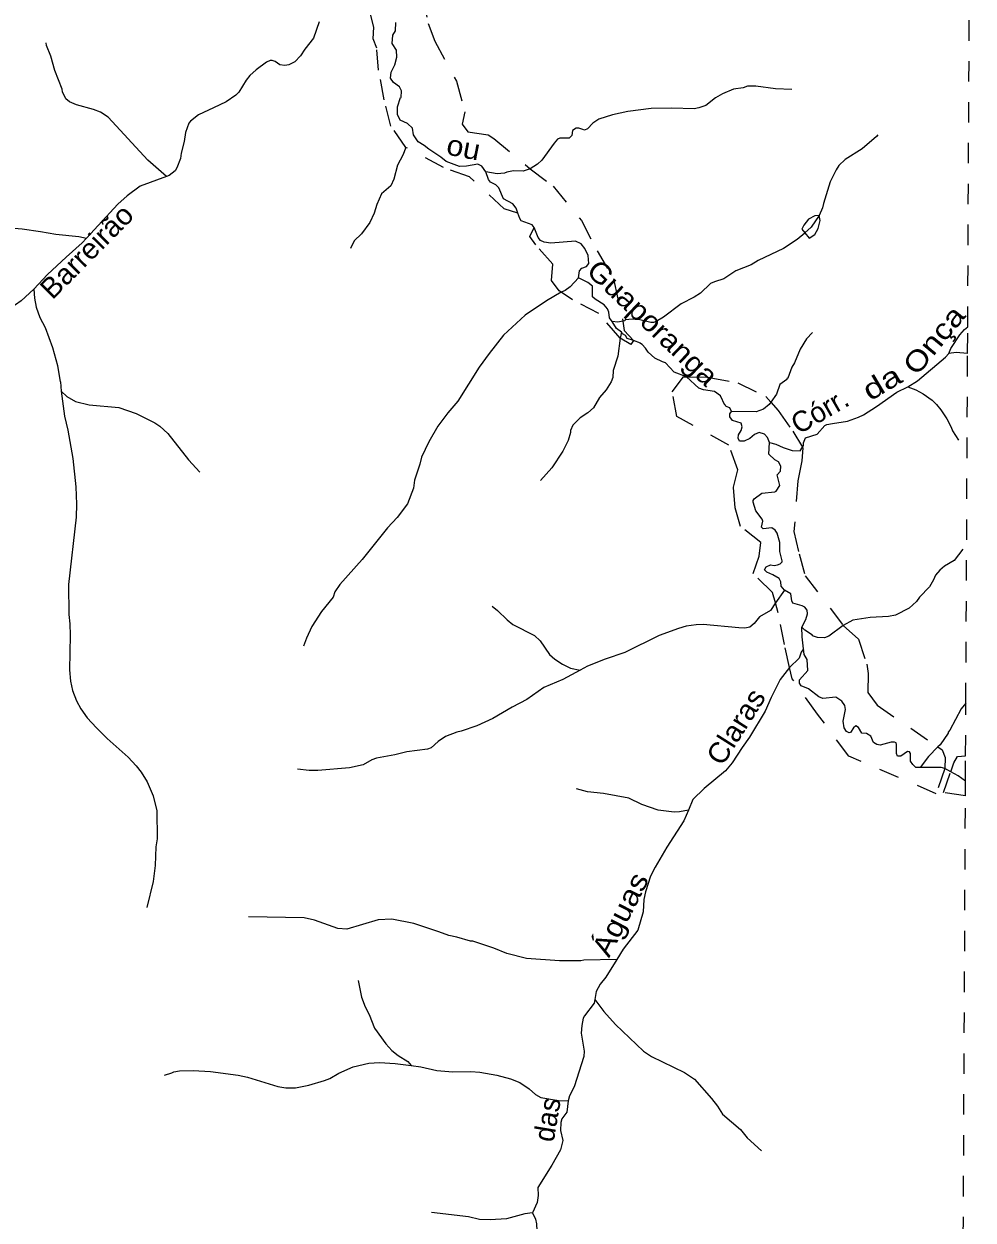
# Model space of a CAD drawing. Extents: x 551.6 to 577.6, y 7567 to 7594.7.
# Drawn here: x 572.91 to 577.56, y 7584.89 to 7590.74 of the extents above; entities that cross this region are included whole.
import ezdxf
from ezdxf.enums import TextEntityAlignment as Align

# ---------------------------------------------------------------- set-up
doc = ezdxf.new("R2010")
doc.units = 0
doc.header["$LTSCALE"] = 0.04
doc.linetypes.add('SHORT_DASHED', pattern=[2.7, 1.5, -1.2])
for name, color, linetype, lineweight in [('2', 7, 'Continuous', 25), ('21', 7, 'SHORT_DASHED', 13), ('53', 7, 'SHORT_DASHED', 13), ('55', 7, 'Continuous', 25), ('7', 7, 'Continuous', 25)]:
    doc.layers.add(name, color=color, linetype=linetype, lineweight=lineweight)
doc.layers.add('61', color=7, linetype='Continuous')

msp = doc.modelspace()

# ---------------------------------------------------------------- linework, layer by layer
at = {"layer": '2'}
for points in [[(576.8021, 7589.8034), (576.7803, 7589.8018), (576.7501, 7589.7864), (576.7265, 7589.7562), (576.7172, 7589.7366), (576.7322, 7589.7187)], [(576.781, 7589.7119), (576.7973, 7589.7407), (576.8076, 7589.7805), (576.8021, 7589.8034)], [(576.7322, 7589.7187), (576.7534, 7589.6932), (576.781, 7589.7119)]]:
    msp.add_lwpolyline(points, dxfattribs=at)
at = {"layer": '21'}
for p, q in [((577.4113, 7586.9802), (577.4465, 7587.0816)), ((577.518, 7586.9644), (577.4113, 7586.9802))]:
    msp.add_line(p, q, dxfattribs=at)
for points in [[(574.7788, 7590.1378), (574.7064, 7590.2422), (574.6729, 7590.3709), (574.6461, 7590.5153), (574.6372, 7590.6224), (574.6201, 7590.6693), (574.6231, 7590.7258), (574.5903, 7590.8538), (574.5501, 7590.8925), (574.4851, 7590.8927)], [(574.8652, 7590.8839), (574.8641, 7590.8725), (574.8879, 7590.7438), (574.9214, 7590.6567), (575.0267, 7590.4621), (575.0688, 7590.3122), (575.0554, 7590.2519), (575.0833, 7590.2143), (575.1823, 7590.1987), (575.2106, 7590.1816), (575.3873, 7590.0333)], [(575.3278, 7589.8154), (575.2602, 7589.8375), (575.0913, 7589.993), (574.9632, 7590.0391), (574.7788, 7590.1378)], [(575.3873, 7590.0333), (575.5009, 7589.9472), (575.6393, 7589.7798), (575.7153, 7589.6309), (575.7953, 7589.4936), (575.8416, 7589.287)], [(575.5402, 7589.4283), (575.5304, 7589.4349), (575.4917, 7589.4855), (575.4985, 7589.5666), (575.4151, 7589.6604), (575.3868, 7589.702), (575.408, 7589.7462)], [(575.8281, 7589.2037), (575.7239, 7589.3247), (575.5944, 7589.3917), (575.5402, 7589.4283)], [(575.8416, 7589.287), (575.8475, 7589.2414), (575.8935, 7589.1929)], [(575.8935, 7589.1929), (575.8802, 7589.173), (575.8281, 7589.2037)], [(576.5882, 7587.9092), (576.5744, 7587.9589), (576.4784, 7588.0522), (576.5085, 7588.1372), (576.5168, 7588.203), (576.418, 7588.2825), (576.3905, 7588.373), (576.3823, 7588.4745), (576.4043, 7588.5595), (576.3604, 7588.6802), (576.1052, 7588.82), (576.0833, 7588.9407), (576.1382, 7589.0147), (576.1523, 7589.0144)], [(576.1523, 7589.0144), (576.2644, 7589.012), (576.4044, 7588.9846), (576.5416, 7588.9187), (576.566, 7588.891)], [(576.566, 7588.891), (576.6019, 7588.8502), (576.6733, 7588.7487), (576.7206, 7588.67)], [(576.7206, 7588.67), (576.7227, 7588.6665), (576.7172, 7588.6034), (576.698, 7588.5047), (576.6788, 7588.2578), (576.7035, 7588.1481), (576.7337, 7588.0412), (576.92, 7587.7979)], [(576.6578, 7587.5914), (576.632, 7587.7039), (576.6018, 7587.8602), (576.5882, 7587.9092)], [(576.92, 7587.7979), (576.9944, 7587.7313), (577.0347, 7587.6079), (577.0425, 7587.5625), (577.0406, 7587.4689), (577.0859, 7587.4078), (577.3828, 7587.203)], [(577.4169, 7587.0981), (577.3748, 7586.9743), (576.9469, 7587.1582), (576.7939, 7587.3639), (576.6704, 7587.5366), (576.6578, 7587.5914)], [(577.3828, 7587.203), (577.4044, 7587.1881), (577.4192, 7587.1516), (577.4169, 7587.0981)], [(577.4465, 7587.0816), (577.4616, 7587.125), (577.4793, 7587.1566), (577.519, 7587.1599)]]:
    msp.add_lwpolyline(points, dxfattribs=at)
at = {"layer": '53'}
msp.add_lwpolyline([(577.4204, 7566.9518), (577.4226, 7567.3928), (577.4384, 7570.6314), (577.4446, 7571.9213), (577.4462, 7572.242), (577.4659, 7576.2813), (577.4696, 7577.0412), (577.4755, 7578.252), (577.4832, 7579.8317), (577.4989, 7583.0336), (577.5065, 7584.6034), (577.518, 7586.9644), (577.5184, 7587.0352), (577.519, 7587.1599), (577.5202, 7587.417), (577.5286, 7589.1281), (577.5292, 7589.2596), (577.5446, 7592.4063), (577.549, 7593.3187), (577.5554, 7594.6251)], dxfattribs=at)
at = {"layer": '55'}
msp.add_lwpolyline([(576.8021, 7589.8034), (576.7637, 7589.747), (576.7322, 7589.7187), (576.732, 7589.7185)], dxfattribs=at)
at = {"layer": '7'}
for p, q in [((575.835, 7589.2333), (575.8281, 7589.2037)), ((576.6324, 7587.9708), (576.5882, 7587.9092))]:
    msp.add_line(p, q, dxfattribs=at)
for points in [[(574.3546, 7590.7519), (574.3281, 7590.6722), (574.2846, 7590.6183), (574.2645, 7590.5861), (574.2363, 7590.5555), (574.2074, 7590.541), (574.1865, 7590.5386), (574.1631, 7590.541), (574.1398, 7590.5579), (574.1253, 7590.5627), (574.1156, 7590.5627), (574.0979, 7590.5539), (574.0464, 7590.5169), (574.0158, 7590.4895), (573.9981, 7590.467), (573.9627, 7590.4082), (573.9466, 7590.3929), (573.9, 7590.3607), (573.8388, 7590.331)], [(574.839, 7590.1647), (574.8177, 7590.1993), (574.8126, 7590.2312), (574.7868, 7590.2537), (574.7514, 7590.2706), (574.7385, 7590.298), (574.7386, 7590.3359), (574.7534, 7590.3815), (574.7562, 7590.3817), (574.7578, 7590.4139), (574.7482, 7590.4332), (574.7192, 7590.4549), (574.7039, 7590.4766), (574.7071, 7590.5056), (574.7257, 7590.541), (574.7349, 7590.579), (574.7334, 7590.6136), (574.7128, 7590.646), (574.7157, 7590.6873), (574.7283, 7590.7087), (574.7298, 7590.7485)], [(573.6077, 7589.9951), (573.516, 7590.0742), (573.3229, 7590.2851), (573.2851, 7590.31), (573.2513, 7590.3237), (573.1676, 7590.3454), (573.1338, 7590.3599), (573.1161, 7590.3752), (573.0984, 7590.409), (573.0967, 7590.4219), (573.0613, 7590.5137), (573.042, 7590.5845), (573.0211, 7590.636), (573.0187, 7590.6497)], [(576.6677, 7590.4203), (576.588, 7590.4235), (576.493, 7590.4364), (576.4512, 7590.4364), (576.4302, 7590.4291), (576.3836, 7590.4219), (576.3288, 7590.4002), (576.295, 7590.3809), (576.2468, 7590.343), (576.2129, 7590.3318), (576.1904, 7590.3269), (576.081, 7590.3294), (575.9796, 7590.3277), (575.8653, 7590.3133), (575.7912, 7590.2964), (575.7236, 7590.2762), (575.6938, 7590.2553), (575.6689, 7590.2288), (575.6544, 7590.2215), (575.6448, 7590.2247)], [(573.8388, 7590.331), (573.7647, 7590.2972), (573.7253, 7590.2666), (573.718, 7590.2561), (573.7003, 7590.2111), (573.6939, 7590.166), (573.6794, 7590.1089), (573.6762, 7590.0839), (573.6585, 7590.0372), (573.6497, 7590.0235), (573.6215, 7590.0002), (573.6077, 7589.9951)], [(575.6448, 7590.2247), (575.6254, 7590.2312), (575.6125, 7590.2312), (575.5948, 7590.2199), (575.5916, 7590.1958), (575.5795, 7590.1829), (575.5337, 7590.1829), (575.5224, 7590.1772), (575.5047, 7590.1587), (575.4452, 7590.075), (575.4242, 7590.0549), (575.3873, 7590.0333)], [(577.0886, 7590.199), (577.0821, 7590.1901), (577.0129, 7590.1306), (576.9292, 7590.0775), (576.8986, 7590.0493), (576.8849, 7590.0276), (576.8568, 7589.9696), (576.823, 7589.8634), (576.8189, 7589.8409), (576.8021, 7589.8034)], [(574.7788, 7590.1378), (574.7643, 7590.1), (574.7385, 7590.0501), (574.72, 7589.9825), (574.7056, 7589.9495), (574.6605, 7589.9101), (574.6371, 7589.8586), (574.6243, 7589.8159), (574.6025, 7589.77), (574.5623, 7589.7137), (574.5261, 7589.6799), (574.5084, 7589.6421)], [(575.1706, 7590.0176), (575.1507, 7590.0463), (575.1313, 7590.0557), (575.0766, 7590.046), (575.0412, 7590.0444), (574.977, 7590.0681), (574.951, 7590.0903), (574.8915, 7590.1289), (574.8689, 7590.1474), (574.839, 7590.1647)], [(572.0883, 7590.0759), (572.1841, 7590.0597), (572.2372, 7590.0372), (572.2887, 7590.0219), (572.3403, 7589.9962), (572.469, 7589.9406), (572.5189, 7589.906), (572.5455, 7589.8916), (572.5842, 7589.8514), (572.6155, 7589.8111), (572.6396, 7589.7861), (572.6565, 7589.7732), (572.6815, 7589.7612), (572.704, 7589.7547), (572.902, 7589.7394), (572.9921, 7589.7266), (573.0662, 7589.7121)], [(575.3873, 7590.0333), (575.3534, 7590.0211), (575.3067, 7590.0227), (575.2729, 7590.0163), (575.2617, 7590.0106), (575.2267, 7590.008), (575.1706, 7590.0176)], [(575.3278, 7589.8154), (575.3195, 7589.8398), (575.3033, 7589.8612), (575.2572, 7589.8851), (575.2344, 7589.9389), (575.2204, 7589.9537), (575.1941, 7589.968), (575.1836, 7589.9809), (575.1706, 7590.0176)], [(573.6077, 7589.9951), (573.4798, 7589.9479), (573.4163, 7589.9012), (573.3704, 7589.8594), (573.2166, 7589.6935)], [(575.408, 7589.7462), (575.3969, 7589.758), (575.3439, 7589.7786), (575.3365, 7589.7897), (575.3278, 7589.8154)], [(575.625, 7589.4998), (575.6291, 7589.5328), (575.6413, 7589.5457), (575.6634, 7589.5538), (575.6752, 7589.5685), (575.6722, 7589.6076), (575.6556, 7589.6419), (575.6372, 7589.6654), (575.6099, 7589.678), (575.4886, 7589.6694), (575.4564, 7589.6742), (575.4386, 7589.6825), (575.4264, 7589.6961), (575.408, 7589.7462)], [(573.0662, 7589.7121), (573.1789, 7589.7008), (573.2166, 7589.6935)], [(573.2166, 7589.6935), (573.1957, 7589.671), (573.1169, 7589.6002)], [(576.732, 7589.7185), (576.695, 7589.6863), (576.6282, 7589.642), (576.5035, 7589.5841), (576.4689, 7589.5632), (576.3948, 7589.5326), (576.3353, 7589.4948), (576.2902, 7589.4803), (576.2709, 7589.4706), (576.221, 7589.4248), (576.1904, 7589.4046), (576.1276, 7589.3716), (576.0407, 7589.3065), (576.0037, 7589.2855), (575.9908, 7589.2799), (575.9779, 7589.2807), (575.9175, 7589.2955), (575.8887, 7589.2969), (575.8533, 7589.2933), (575.8508, 7589.2888), (575.8416, 7589.287)], [(573.1169, 7589.6002), (573.0259, 7589.5157), (572.9581, 7589.4442)], [(575.625, 7589.4998), (575.5837, 7589.4548), (575.5594, 7589.4364), (575.5402, 7589.4283)], [(575.7884, 7589.2854), (575.7767, 7589.3033), (575.7735, 7589.3314), (575.767, 7589.3475), (575.7502, 7589.3668), (575.7054, 7589.3939), (575.6932, 7589.4068), (575.6925, 7589.4591), (575.6704, 7589.4768), (575.625, 7589.4998)], [(572.9581, 7589.4442), (572.8964, 7589.3869), (572.8698, 7589.3676), (572.8392, 7589.3523), (572.8183, 7589.3483), (572.7555, 7589.3588), (572.7362, 7589.3588), (572.6589, 7589.329), (572.6203, 7589.2992), (572.6012, 7589.2752)], [(572.9581, 7589.4442), (572.9615, 7589.3998), (572.9704, 7589.3548), (572.9881, 7589.3049), (573.0138, 7589.2566), (573.0509, 7589.1584), (573.0742, 7589.0699), (573.0871, 7588.9901), (573.0896, 7588.9901), (573.0933, 7588.9451)], [(575.5402, 7589.4283), (575.4677, 7589.3869), (575.3639, 7589.3169), (575.2568, 7589.2179), (575.1876, 7589.1294), (575.1385, 7589.0618), (575.0339, 7588.896), (574.9848, 7588.8381), (574.9357, 7588.7737), (574.8914, 7588.6964), (574.856, 7588.6208), (574.848, 7588.587), (574.8222, 7588.5081), (574.8166, 7588.4695), (574.7876, 7588.3922)], [(575.8416, 7589.287), (575.817, 7589.2823), (575.7884, 7589.2854)], [(575.835, 7589.2333), (575.8105, 7589.2517), (575.7884, 7589.2854)], [(577.436, 7589.1282), (577.447, 7589.154), (577.4909, 7589.2196), (577.5127, 7589.2461), (577.5292, 7589.2596)], [(575.8281, 7589.2037), (575.817, 7589.1149), (575.7944, 7589.0457), (575.792, 7589.0119), (575.7848, 7588.9894), (575.759, 7588.9507), (575.7276, 7588.9137), (575.6979, 7588.8622), (575.6705, 7588.8381), (575.6327, 7588.8131), (575.5973, 7588.7777), (575.5852, 7588.752), (575.5852, 7588.7415), (575.5739, 7588.7029), (575.5482, 7588.6514), (575.4934, 7588.5693), (575.4387, 7588.5073)], [(575.8935, 7589.1929), (575.8628, 7589.2018), (575.854, 7589.2163), (575.8395, 7589.2243), (575.835, 7589.2333)], [(576.7691, 7589.2316), (576.7401, 7589.2002), (576.7095, 7589.1503), (576.6813, 7589.0827), (576.6684, 7589.0618), (576.6483, 7589.0075), (576.6443, 7589.0071), (576.6443, 7589.0023), (576.6105, 7588.9765), (576.5936, 7588.9298), (576.566, 7588.891)], [(576.0359, 7589.0883), (575.9972, 7589.1053), (575.9659, 7589.1358), (575.9522, 7589.1552), (575.9361, 7589.1729), (575.928, 7589.1769), (575.928, 7589.1801), (575.8935, 7589.1929)], [(576.1523, 7589.0144), (576.093, 7589.0376), (576.0503, 7589.0827), (576.0359, 7589.0883)], [(577.2833, 7588.995), (577.4201, 7589.1109), (577.436, 7589.1282)], [(577.5286, 7589.1281), (577.4733, 7589.1342), (577.436, 7589.1282)], [(576.373, 7588.8456), (576.3649, 7588.8626), (576.3464, 7588.87), (576.3433, 7588.8759), (576.3401, 7588.8759), (576.3191, 7588.9218), (576.2902, 7588.9435), (576.2354, 7588.9514), (576.2125, 7588.9595), (576.1523, 7589.0144)], [(576.7206, 7588.67), (576.7248, 7588.6787), (576.7248, 7588.6916), (576.7361, 7588.7165), (576.7932, 7588.7334), (576.8294, 7588.7761), (576.8391, 7588.7809), (576.8681, 7588.7866), (576.9405, 7588.7978), (576.9952, 7588.8179), (577.0185, 7588.8292), (577.0829, 7588.8694), (577.1827, 7588.9395), (577.2358, 7588.9652), (577.2833, 7588.995)], [(577.2358, 7588.9652), (577.2753, 7588.9515), (577.3107, 7588.9314), (577.3549, 7588.9008), (577.3767, 7588.8799), (577.3984, 7588.8533), (577.4266, 7588.8091), (577.4475, 7588.7689), (577.4539, 7588.7495), (577.4837, 7588.7053)], [(573.0933, 7588.9451), (573.1096, 7588.822), (573.1257, 7588.7528), (573.1499, 7588.6143), (573.1643, 7588.4759), (573.1676, 7588.3906)], [(573.0933, 7588.9451), (573.1209, 7588.9185), (573.1628, 7588.8944), (573.2304, 7588.8767), (573.3752, 7588.8638), (573.4589, 7588.8348), (573.5515, 7588.7898), (573.5756, 7588.7737), (573.6142, 7588.7367), (573.7156, 7588.6079), (573.7712, 7588.5475)], [(576.5596, 7588.6932), (576.5492, 7588.7175), (576.5345, 7588.7337), (576.5079, 7588.7426), (576.4851, 7588.7322), (576.4633, 7588.7134), (576.4357, 7588.6998), (576.4128, 7588.699), (576.4054, 7588.7145), (576.4069, 7588.73), (576.4209, 7588.7521), (576.4246, 7588.7705), (576.4202, 7588.7882), (576.3781, 7588.8007), (576.3656, 7588.8184), (576.3656, 7588.8339), (576.373, 7588.8456)], [(576.566, 7588.891), (576.5572, 7588.8787), (576.5299, 7588.8566), (576.4938, 7588.8426), (576.373, 7588.8456)], [(576.5976, 7588.0944), (576.6121, 7588.0992), (576.621, 7588.1089), (576.6218, 7588.1137), (576.6105, 7588.1604), (576.6089, 7588.2039), (576.5968, 7588.249), (576.5871, 7588.2643), (576.5713, 7588.275), (576.5289, 7588.2709), (576.5201, 7588.2791), (576.5268, 7588.3077), (576.5228, 7588.3182), (576.4922, 7588.3584), (576.4785, 7588.4019), (576.4785, 7588.4099), (576.4841, 7588.418), (576.522, 7588.4453), (576.5848, 7588.4517), (576.5912, 7588.455), (576.6093, 7588.4822), (576.5967, 7588.5345), (576.6122, 7588.5522), (576.6144, 7588.5779), (576.6026, 7588.5978), (576.5857, 7588.6089), (576.5555, 7588.6361), (576.5596, 7588.6932)], [(576.5596, 7588.6932), (576.5908, 7588.6848), (576.6266, 7588.6682), (576.6701, 7588.6546), (576.7087, 7588.653), (576.7206, 7588.67)], [(573.1676, 7588.3906), (573.166, 7588.3278), (573.1289, 7587.9979), (573.1305, 7587.8514), (573.1354, 7587.8063), (573.137, 7587.75), (573.133, 7587.581), (573.1386, 7587.5246), (573.1474, 7587.4796), (573.1684, 7587.4281), (573.1893, 7587.3894)], [(574.7876, 7588.3922), (574.7369, 7588.3262), (574.6894, 7588.2747), (574.5655, 7588.121), (574.456, 7587.9979), (574.4327, 7587.9625), (574.4231, 7587.9367), (574.3667, 7587.8667), (574.32, 7587.7918), (574.2927, 7587.7355), (574.279, 7587.6961)], [(577.5046, 7588.1709), (577.4628, 7588.1161), (577.4153, 7588.088), (577.392, 7588.0687), (577.3718, 7588.0445), (577.3622, 7588.0204), (577.3429, 7587.9866), (577.293, 7587.9359), (577.2785, 7587.9142), (577.2431, 7587.8828), (577.1755, 7587.8482), (577.1417, 7587.8417), (577.0516, 7587.8361), (576.9662, 7587.824), (576.92, 7587.7979)], [(576.6324, 7587.9708), (576.6169, 7587.9907), (576.6147, 7588.0106), (576.6058, 7588.0276), (576.5756, 7588.046), (576.5461, 7588.059), (576.5352, 7588.0694), (576.5429, 7588.0838), (576.5636, 7588.0941), (576.5813, 7588.0919), (576.5976, 7588.0944)], [(576.718, 7587.7888), (576.7371, 7587.8271), (576.7448, 7587.8547), (576.7441, 7587.8724), (576.7323, 7587.8864), (576.7183, 7587.8932), (576.6729, 7587.906), (576.6678, 7587.9185), (576.6633, 7587.9524), (576.6324, 7587.9708)], [(576.5882, 7587.9092), (576.5646, 7587.8707), (576.5099, 7587.8393), (576.4833, 7587.8079), (576.4632, 7587.7894), (576.4383, 7587.7846), (576.4093, 7587.7854), (576.2339, 7587.8031), (576.2001, 7587.8015), (576.1518, 7587.7934), (576.114, 7587.783), (576.0198, 7587.7484), (575.8508, 7587.6647), (575.7542, 7587.6325)], [(575.2013, 7587.8924), (575.2287, 7587.8715), (575.2754, 7587.8248), (575.3027, 7587.8031), (575.4097, 7587.7492), (575.4371, 7587.7226), (575.4822, 7587.655), (575.5079, 7587.6325), (575.5466, 7587.6083), (575.5852, 7587.589), (575.6327, 7587.5787)], [(576.92, 7587.7979), (576.8487, 7587.7451), (576.8278, 7587.7363), (576.794, 7587.7387), (576.7699, 7587.7475), (576.7699, 7587.75), (576.7319, 7587.7739), (576.718, 7587.7888)], [(576.7262, 7587.6839), (576.7187, 7587.7417), (576.718, 7587.7888)], [(576.7262, 7587.6839), (576.7135, 7587.6663), (576.7039, 7587.6381), (576.6578, 7587.5914)], [(577.2961, 7587.1026), (577.2756, 7587.1025), (577.2608, 7587.1165), (577.249, 7587.1335), (577.2498, 7587.171), (577.2439, 7587.1793), (577.2342, 7587.181), (577.2013, 7587.158), (577.1858, 7587.158), (577.1814, 7587.1705), (577.1806, 7587.2154), (577.1784, 7587.2228), (577.1711, 7587.2268), (577.1545, 7587.2257), (577.1014, 7587.2124), (577.0845, 7587.2154), (577.0682, 7587.2242), (577.055, 7587.2566), (577.0336, 7587.2684), (577.0111, 7587.271), (576.9942, 7587.299), (576.9816, 7587.3063), (576.9706, 7587.2968), (576.9558, 7587.2743), (576.9485, 7587.2727), (576.9365, 7587.2783), (576.9244, 7587.2969), (576.9203, 7587.3297), (576.9318, 7587.3865), (576.9273, 7587.4057), (576.9133, 7587.427), (576.8838, 7587.4469), (576.8204, 7587.4403), (576.8005, 7587.4477), (576.7493, 7587.4871), (576.7146, 7587.5026), (576.7065, 7587.5151), (576.7065, 7587.5321), (576.747, 7587.5777), (576.7434, 7587.6308), (576.7283, 7587.6562), (576.7262, 7587.6839)], [(575.7542, 7587.6325), (575.6677, 7587.5976), (575.6327, 7587.5787)], [(575.6327, 7587.5787), (575.5474, 7587.5327), (575.4548, 7587.494), (575.3719, 7587.4345), (575.2995, 7587.3975), (575.2053, 7587.3419), (575.1265, 7587.3057), (575.0508, 7587.28), (575.0283, 7587.2751), (574.9743, 7587.2534), (574.9381, 7587.2301), (574.9035, 7587.1987), (574.885, 7587.1914), (574.7836, 7587.1786)], [(576.6578, 7587.5914), (576.6113, 7587.5327), (576.567, 7587.4458), (576.5373, 7587.3782), (576.4608, 7587.251), (576.4246, 7587.2011), (576.3771, 7587.1247), (576.3441, 7587.0868), (576.2387, 7586.9991), (576.184, 7586.946), (576.1624, 7586.8944)], [(573.1893, 7587.3894), (573.2191, 7587.346), (573.2658, 7587.2961), (573.3172, 7587.2446), (573.4211, 7587.1528), (573.4597, 7587.111), (573.4839, 7587.0788), (573.5128, 7587.0321), (573.5426, 7586.9645), (573.5603, 7586.8905), (573.5619, 7586.7536), (573.5555, 7586.7134), (573.5531, 7586.6233), (573.5426, 7586.5444), (573.5112, 7586.4164)], [(577.5202, 7587.417), (577.4966, 7587.3894), (577.4419, 7587.2856), (577.433, 7587.2759), (577.433, 7587.2711), (577.3936, 7587.214), (577.3828, 7587.203)], [(574.7836, 7587.1786), (574.7257, 7587.1641), (574.6355, 7587.148), (574.613, 7587.1399), (574.5712, 7587.1158), (574.5036, 7587.1013), (574.349, 7587.0884), (574.3056, 7587.0876), (574.25, 7587.0949)], [(577.3828, 7587.203), (577.3365, 7587.1562), (577.2961, 7587.1026)], [(577.4169, 7587.0981), (577.3992, 7587.1029), (577.2961, 7587.1026)], [(577.5184, 7587.0352), (577.4821, 7587.0619), (577.4465, 7587.0816), (577.4169, 7587.0981)], [(576.1624, 7586.8944), (576.118, 7586.8848), (576.0922, 7586.8832), (576.015, 7586.8929), (575.9345, 7586.921), (575.8701, 7586.9516), (575.7462, 7586.9758), (575.6689, 7586.9838), (575.615, 7586.9983)], [(576.1624, 7586.8944), (576.1397, 7586.8406), (576.056, 7586.7118), (575.9989, 7586.6152)], [(575.9989, 7586.6152), (575.9771, 7586.5702), (575.9522, 7586.4945), (575.9441, 7586.4559), (575.9409, 7586.3963), (575.9151, 7586.3062), (575.8427, 7586.2128), (575.8119, 7586.1629)], [(574.9414, 7586.2973), (574.819, 7586.3384), (574.7112, 7586.3593), (574.6436, 7586.3561), (574.4907, 7586.311), (574.4472, 7586.3142), (574.3329, 7586.3544), (574.2814, 7586.3665), (574.0086, 7586.3722)], [(575.8119, 7586.1629), (575.6512, 7586.1597), (575.6351, 7586.1565), (575.5321, 7586.1565), (575.3695, 7586.1677), (575.2729, 7586.1919), (575.2102, 7586.2176), (575.1072, 7586.2522), (575.0959, 7586.2522), (575.0283, 7586.2724), (574.9897, 7586.2804), (574.9414, 7586.2973)], [(575.8119, 7586.1629), (575.7582, 7586.076), (575.7309, 7586.0422), (575.7115, 7586.0068), (575.7045, 7585.9676)], [(574.5454, 7586.0591), (574.5631, 7585.9778), (574.58, 7585.9311), (574.5993, 7585.8941), (574.6259, 7585.8265), (574.6822, 7585.7493), (574.7112, 7585.7171), (574.7418, 7585.6921), (574.7884, 7585.6639), (574.8049, 7585.6437)], [(575.7045, 7585.9676), (575.7011, 7585.9488), (575.6544, 7585.8877), (575.648, 7585.8748), (575.6399, 7585.8394), (575.6367, 7585.8024), (575.652, 7585.7138), (575.6512, 7585.6881), (575.6029, 7585.54), (575.5804, 7585.4949), (575.5731, 7585.471)], [(575.7045, 7585.9676), (575.7486, 7585.9078), (575.8057, 7585.8442), (575.9425, 7585.7138), (575.9812, 7585.6873), (576.1437, 7585.6092), (576.1928, 7585.5762), (576.2757, 7585.4821), (576.3047, 7585.445), (576.3296, 7585.4056), (576.4165, 7585.33), (576.4496, 7585.2905), (576.5196, 7585.2269)], [(573.5982, 7585.5971), (573.6344, 7585.6076), (573.6432, 7585.6132), (573.6714, 7585.6172), (573.739, 7585.6189), (573.8227, 7585.614), (573.9595, 7585.5963), (574.0046, 7585.5875), (574.1527, 7585.5416), (574.1913, 7585.5352), (574.2396, 7585.5352), (574.304, 7585.548), (574.3812, 7585.5706), (574.407, 7585.581), (574.4512, 7585.606), (574.5213, 7585.6366), (574.5985, 7585.6551), (574.65, 7585.6591), (574.7273, 7585.6543), (574.8049, 7585.6437), (574.8521, 7585.6373)], [(574.8521, 7585.6373), (574.9317, 7585.6189), (575.009, 7585.6124), (575.0975, 7585.614), (575.141, 7585.6108), (575.2247, 7585.5963), (575.2923, 7585.5786), (575.3373, 7585.5601), (575.3824, 7585.5295), (575.4138, 7585.5022), (575.4403, 7585.4869), (575.5273, 7585.4724), (575.5731, 7585.471)], [(575.5731, 7585.471), (575.5667, 7585.4161), (575.5433, 7585.3831), (575.5385, 7585.3646), (575.5361, 7585.3259), (575.5482, 7585.276), (575.5361, 7585.231), (575.4942, 7585.1553), (575.4258, 7585.0467), (575.4274, 7585.0072), (575.4226, 7584.9734), (575.3989, 7584.9221)], [(575.3989, 7584.9221), (575.3615, 7584.9171), (575.2713, 7584.8929), (575.1925, 7584.8881), (575.1401, 7584.8905), (575.0862, 7584.9034), (574.9051, 7584.9243)], [(575.3989, 7584.9221), (575.4146, 7584.8913), (575.4194, 7584.8688), (575.421, 7584.835), (575.4266, 7584.8012), (575.4379, 7584.761), (575.4419, 7584.7223), (575.425, 7584.6419), (575.427, 7584.6289), (575.4307, 7584.6044)]]:
    msp.add_lwpolyline(points, dxfattribs=at)

# ---------------------------------------------------------------- texts
at = {"layer": '61'}
for s, rotation, width, p in [('ou', 348.99, 1.1, (575.0527, 7590.0885)), ('Barreirão', 45.297, 1.05, (573.2528, 7589.5931)), ('Guaporanga', 316.357, 1.1, (575.9532, 7589.243)), ('Onça', 50.639, 1.2, (577.4024, 7589.1632)), ('da', 30.712, 1.3, (577.1346, 7588.9432)), ('Claras', 57.675, 1.05, (576.4367, 7587.276)), ('Águas', 63.001, 1.15, (575.873, 7586.3614))]:
    msp.add_text(s, height=0.1, rotation=rotation, dxfattribs=dict(at, width=width)).set_placement(p, align=Align.CENTER)
for s, rotation, p in [('Córr.', 29.999, (576.8301, 7588.8048)), ('das', 80.299, (575.5204, 7585.3713))]:
    msp.add_text(s, height=0.1, rotation=rotation, dxfattribs=at).set_placement(p, align=Align.CENTER)

doc.saveas('drawing.dxf')
